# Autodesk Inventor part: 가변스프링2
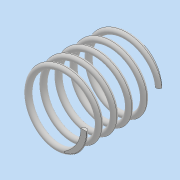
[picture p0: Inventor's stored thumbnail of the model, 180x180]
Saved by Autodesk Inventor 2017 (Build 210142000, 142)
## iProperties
Part Number: 가변스프링2
Material: 일반
Document SubType Name: Modeling
Designer: MRC
Density: 1 g/cm^3
Appearance: 기본값
Author: MRC
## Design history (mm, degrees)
sketch "스케치1"
  geometry: L1 (0, 0)-(11, 0); L2 (11, 0)-(11, 26.358); L3 (11, 26.358)-(0, 26.358); L4 (0, 26.358)-(0, 0); C1 r 1 at (11, 0)
  constraints: 8 end point, 2 parallel, 1 centre point, 1 coincident, 1 horizontal, 1 perpendicular
  dimensions: "d0" = 22 diameter of L2 L4; "d1" = 2 diameter of C1; "d2" = 26.35829 distance between parallel lines of L1 L3 (derived)
feature "코일1" sketch "스케치1" pitch "d3" = 10; turns "d5" = 5; dims "d4" = 26.35829 (= d2), "d6" = 0, angle "d7" = 90 deg, angle "d8" = 90 deg, "d9" = 0, "d10" = 0
sketch "스케치2"
  geometry: L1 (-25.076, 26.358)-(25.076, 26.358); L2 (25.076, 26.358)-(25.076, 0); L3 (25.076, 0)-(-25.076, 0); L4 (-25.076, 0)-(-25.076, 26.358); L5 (0, 26.358)-(0, 0) reference; 2 further points
  constraints: 8 end point, 2 midpoint, 2 parallel, 1 coincident, 1 horizontal, 1 perpendicular
  dimensions: "d11" = 50.15108 distance of L1.start L1.end
extrude "돌출1" sketch "스케치2" stored distance "d12" = 0; taper "d13" = 0 deg
node "솔리드1"
